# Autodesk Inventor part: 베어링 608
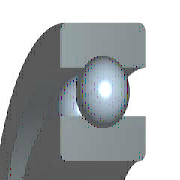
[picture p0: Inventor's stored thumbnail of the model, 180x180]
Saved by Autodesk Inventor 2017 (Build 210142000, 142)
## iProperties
IsCustomPart: 1
Created: 2012-02
Part Number: 베어링 608
Material: 강철, 연강
Description: 깊은 그루브 볼 베어링
Document SubType Name: Modeling
Standard: KS B 2023
Designer: mduedu
Standards Organization: KS
Language: ko-KR
Size Designation: 608 - 8 x 22 x 7
Categories: <MemberInstance><Categories><Category DisplayName="샤프트 부품" InternalName="7f7aeb1f-a693-4053-b835-cee3144e0d98" Mnemonic="SHFT"><Category DisplayName="베어링" Inter
Density: 1 g/cm^3
Appearance: 보라색
Author: mduedu
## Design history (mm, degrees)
sketch "스케치" dims "d0" = 3.64 (= -0.26 x WD + 0.26 x BD)
  geometry: L1 (1.68, 7.5)-(5.32, 7.5); L2 (3.5, 7.5)-(3.5, 5.68); L3 (3.5, 7.5)-(3.5, 9.32); L4 (2.148, 6.282)-(0, 6.282); L5 (0, 4)-(7, 4); L6 (2.148, 8.718)-(0, 8.718); L7 (0, 11)-(7, 11); L8 (7, 4)-(7, 6.282); L9 (4.852, 6.282)-(7, 6.282); L10 (4.852, 8.718)-(7, 8.718); L11 (7, 11)-(7, 8.718); L12 (-1.4, 0)-(8.4, 0) reference; L13 (0, -0.3)-(0, 5.3) reference
  constraints: 22 end point, 4 point on line, 2 collinear, 2 perpendicular, 2 symmetric about line, 1 midpoint, 1 parallel, 14 other
  dimensions: "d9" = 8 diameter of L5 L12 (= WD); "d11" = 22 diameter of L7 L12 (= BD); "d12" = 7 distance between parallel lines of L8 L13 (= KB); "d13" = 12.564 diameter of L9 L12 (= 0.326 x BD + 0.674 x WD)
revolve "본체" stored, may be unused: angle "d6" = 90 deg
revolve "볼" stored, may be unused: angle "d7" = 90 deg
pattern_circular "IDS_ARRAYBALL[SIMPL:T]" dims angle "d3" = 360 deg
body "Solid1"
fillet "모깎기1" dims "d1" = 0.3 (= KRS)
other parameters: "WD" = 8 [user parameter; used in 5 equation terms], "BD" = 22 [user parameter; used in 5 equation terms], "KB" = 7 [user parameter; used in 1 equation term], "KRS" = 0.3 [user parameter; used in 1 equation term], "d4" = 0, "d5" = 0, "d8" = 0, "d14" = 0, "d15" = 0, "BBA" = 0 [user parameter], "BC0" = 1370000 [user parameter], "BC" = 3250000 [user parameter], "BR" = 11 (= 0.5 x BD) [user parameter], "WR" = 4 (= 0.5 x WD) [user parameter]
